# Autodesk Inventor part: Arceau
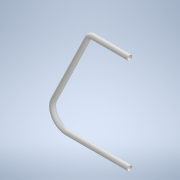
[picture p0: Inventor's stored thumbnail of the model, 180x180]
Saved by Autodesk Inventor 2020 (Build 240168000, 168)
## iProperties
Created: 2021-01
Part Number: Arceau
Material: Générique
Document SubType Name: Modeling
Designer: bruno
Density: 1 g/cm^3
Appearance: Par défaut
Author: bruno
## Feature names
1. Balayage1
## Parameters: d0 = 16 mm, d6 = 0, d7 = 0
